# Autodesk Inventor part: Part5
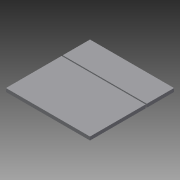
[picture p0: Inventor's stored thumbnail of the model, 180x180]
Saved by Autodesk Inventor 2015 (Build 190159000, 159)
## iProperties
Created: 2015-04
Part Number: Part5
Material: Generic
Document SubType Name: Modeling
Designer: TREINA5
Density: 1 g/cm^3
Appearance: Default
Mass: 129645 g
Surface Area: 48519 cm^2
Volume: 129645 cm^3
Author: TREINA5
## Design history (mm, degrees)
sketch "Sketch1"
  geometry: L1 (13480, 4245.02)-(13480, 3234.98); L2 (13499.999, 4479.966)-(14982.938, 4479.966); L3 (13502.938, 3000)-(13500, 4480); L4 (13499.999, 4499.966)-(14982.938, 4499.966); L5 (14982.938, 4480)-(14982.938, 3000); L6 (12000, 3499.835)-(12000, 3980.098); L7 (12000, 4000)-(12000, 4479.966); L8 (12000, 4479.966)-(12479.966, 4479.966); L9 (11980, 4480)-(11980, 3000); L10 (10500, 3000)-(10500, 4480); L11 (10500, 4480)-(11980, 4480); L12 (12499.868, 4479.966)-(13480, 4479.966); L13 (13480, 3000.034)-(13480, 2999.966); L14 (11500.033, 2980)-(11980, 2980); L15 (11980, 2980)-(11980, 2500); L16 (12000, 1499.966)-(12000, 2480.098); L17 (12000, 1500)-(13480, 1500); L18 (13480, 2745.087)-(13480, 1499.966); L19 (12234.538, 1499.966)-(13480, 1499.966); L20 (12499.868, 2999.966)-(13480, 2999.966); L21 (11480.132, 2979.966)-(13480, 2979.966); L22 (11980, 2480.098)-(11980, 1500); L23 (12000, 2500)-(12000, 2979.966); L24 (10500, 1480)-(11980, 1480); L25 (10500, 1500)-(11980, 1500); L26 (10500, 1500)-(11745.258, 1500); L27 (10480, 2479.966)-(10480, 1499.966); L28 (10500, 1500)-(10500, 2745.087); L29 (10500, 3000)-(11980, 3000); L30 (10500, 2980)-(11480.131, 2980); L31 (9000, 2999.966)-(9480, 2999.966); L32 (8500, 2999.966)-(8980, 2999.966); L33 (9500, 4479.966)-(9500, 2999.966); L34 (9480, 4479.966)-(9480, 2999.966); L35 (8500, 4479.966)-(8980, 4479.966); L36 (8500, 2999.966)-(8500, 4479.966); L37 (8480, 2999.966)-(8480, 4479.966); L38 (7500, 4479.966)-(8480, 4479.966); L39 (7500, 2999.966)-(8480, 2999.966); L40 (13500, 1480)-(14980, 1480); L41 (14980, 1480)-(14980, 0); L42 (13500, 0)-(13500, 1480); L43 (13500, 0)-(14980, 0); L44 (13500, 1500)-(14565.618, 1500); L45 (14979.989, 1500)-(14980, 1500); L46 (13499.999, 2999.966)-(14982.938, 2999.966); L47 (14982.938, 2980)-(14982.938, 1500); L48 (13499.999, 2979.966)-(14982.938, 2979.966); L49 (13497.05, 1499.966)-(14979.989, 1499.966); L50 (13497.05, 1479.966)-(14979.989, 1479.966); L51 (9000, 1500)-(10480, 1500); L52 (9000, 1480)-(10480, 1480); L53 (9000, 1499.966)-(9000, 2979.966); L54 (9000, 1499.966)-(10480, 1499.966); L55 (9480, 2479.966)-(10480, 2479.966); L56 (9500, 2499.966)-(10480, 2499.966); L57 (10480, 2979.966)-(10480, 2499.966); L58 (9500, 2979.966)-(10480, 2979.966); L59 (9500, 2999.966)-(10480, 2999.966); L60 (9500, 2979.966)-(9500, 2499.966); L61 (9480, 2979.966)-(9480, 2479.966); L62 (7500, 1500)-(8980, 1500); L63 (7500, 1480)-(8980, 1480); L64 (7500, 2979.966)-(8480, 2979.966)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; A1 r 509.966 centre (11990, 4489.966) between (12000, 3980.098) and (12499.869, 4480.001); A2 r 490.068 centre (11990, 4489.966) between (12000, 4000) and (12479.967, 4480.001); A3 r 1490.034 centre (11990, 4489.966) between (13277.537, 3740) and (13480, 4479.966); A4 r 1510 centre (11990, 4489.966) between (13300.591, 3740) and (13480, 4245.02); A5 r 1510 centre (11990, 2990.034) between (13480, 3234.98) and (13300.591, 3740); A6 r 1490.034 centre (11990, 2990.034) between (13480, 2999.966) and (13277.536, 3740); A7 r 490.068 centre (11990, 2989.966) between (11500.033, 2980.001) and (11980, 2500); A8 r 490.068 centre (11990, 2989.966) between (12000, 2500) and (12479.967, 2980.001); A9 r 509.966 centre (11990, 2989.966) between (12000, 2480.098) and (12499.869, 2980.001); A10 r 1510 centre (11990, 2990.034) between (12234.538, 1499.966) and (13480, 2745.087); A11 r 1490.034 centre (11990, 2990.034) between (12000, 1500.034) and (13480, 2979.966); A12 r 509.966 centre (11990, 2989.966) between (11480.131, 2980.001) and (11980, 2480.098); A13 r 1490.034 centre (11990, 2990.034) between (10500, 2980.034) and (11980, 1500.034); A14 r 1510 centre (11990, 2990.034) between (10500, 2745.087) and (11745.258, 1500); A15 r 4510.011 centre (14990, 5990) between (14979.989, 1480) and (14980, 1480); A16 r 1510 centre (11990, 2990.034) between (10480.034, 3000.067) and (10480.033, 2999.966); A17 r 509.966 centre (11990, 2989.966) between (12499.869, 2999.932) and (12000, 3499.835); A18 r 490.068 centre (11990, 2989.966) between (12479.967, 2999.932) and (12000, 3479.933); A19 r 1510 centre (2990, 2489.966) between (2980, 3999.933) and (1568.745, 3000); A20 r 1510 centre (4490, 4490.034) between (2980.033, 4500) and (2980.034, 4480); A21 r 1490.034 centre (2990, 2489.966) between (2980, 3979.966) and (1589.964, 2999.966); A22 r 509.966 centre (2990, 4490) between (3000, 3980.132) and (3499.869, 4480.034); A23 r 490.068 centre (2990, 4490) between (3000, 4000.034) and (3479.967, 4480.034); A24 r 1510 centre (2990, 4490) between (4490.002, 4663.473) and (4489.998, 4663.506); A25 r 1510 centre (5990, 4489.966) between (4490.002, 4663.473) and (4489.998, 4663.439); A26 r 1510 centre (2990, 4490) between (4499.967, 4499.966) and (4499.966, 4500.033); A27 r 1510 centre (5990, 4489.966) between (4480.034, 4479.966) and (4480.034, 4479.933); A28 r 1490.034 centre (2990, 4490) between (3000, 3000) and (4480, 4480); A29 r 1510 centre (2990, 4490) between (3234.742, 2999.966) and (4480, 4245.054); A30 r 1510 centre (5990, 2989.966) between (4480.034, 3000) and (4480.034, 2999.966); A31 r 1510 centre (5990, 4489.966) between (7499.966, 4479.933) and (7499.966, 4479.966); A32 r 1510 centre (5990, 2989.966) between (7499.966, 2999.966) and (7499.966, 3000); A33 r 1510 centre (5990, 2989.966) between (6234.946, 1499.966) and (7480, 2745.02); A34 r 1490.034 centre (5990, 2989.966) between (6000, 1499.966) and (7480, 2979.966); A35 r 509.966 centre (5990, 2989.966) between (6000, 2480.098) and (6499.869, 2980.001); A36 r 490.068 centre (5990, 2989.966) between (5500.033, 2980.001) and (5980, 2500); A37 r 509.966 centre (5990, 2989.966) between (5480.131, 2980.001) and (5980, 2480.098); A38 r 490.068 centre (5990, 2989.966) between (6000, 2500) and (6479.967, 2980.001); A39 r 490.068 centre (2990, 2489.966) between (2980, 2979.933) and (2500.033, 2499.932); A40 r 509.966 centre (2990, 2489.966) between (2848.7, 2979.966) and (2480.132, 2479.966); A41 r 1510 centre (5990, 2989.966) between (4500, 2745.02) and (5745.054, 1499.966); A42 r 1490.034 centre (5990, 2989.966) between (4500, 2979.966) and (5980, 1499.966); A43 r 1510 centre (2990, 2489.966) between (1561.726, 2980) and (1500, 2734.913); A44 r 490.068 centre (11990, 4489.966) between (12479.967, 4499.932) and (12000, 4979.933); A45 r 509.966 centre (11990, 4489.966) between (12499.869, 4499.932) and (12000, 4999.835); A46 r 1490.034 centre (11990, 4489.966) between (13480, 4499.966) and (12000, 5979.966); A47 r 1510 centre (11990, 4489.966) between (13480, 4734.913) and (12234.946, 5979.966); A48 r 1490.034 centre (11990, 4489.966) between (11980, 5979.966) and (10500, 4499.966); A49 r 1510 centre (11990, 4489.966) between (11745.054, 5979.966) and (10500, 4734.913); A50 r 509.966 centre (11990, 4489.966) between (11980, 4999.835) and (11480.131, 4499.932); A51 r 490.068 centre (11990, 4489.966) between (11980, 4979.933) and (11500.033, 4499.932); A52 r 2989.933 centre (13489.917, 8990) between (12000, 6397.733) and (13479.998, 6000.083); A53 r 1510 centre (11990, 4489.966) between (10480.034, 4479.966) and (10480.034, 4479.933); A54 r 3010.067 centre (13489.917, 8990) between (10886.462, 7479.198) and (11979.983, 6386.041); A55 r 2989.933 centre (13489.917, 8990) between (10909.766, 7479.198) and (11979.983, 6409.341); A56 r 3010.067 centre (13489.917, 8990) between (12000, 6374.536) and (13149.912, 5999.198); A57 r 2989.933 centre (13489.917, 8990) between (10500, 8980) and (10898.159, 7499.198); A58 r 3010.067 centre (13489.917, 8990) between (10500, 8642.293) and (10874.958, 7499.198); A59 r 3010.067 centre (13489.917, 8990) between (10479.866, 8980) and (10480, 8959.938); A60 r 490.068 centre (5990, 4489.966) between (6479.967, 4499.932) and (6000, 4979.933); A61 r 1490.034 centre (5990, 4489.966) between (7480, 4499.966) and (6000, 5979.966); A62 r 1510 centre (5990, 4489.966) between (7480, 4734.913) and (6234.946, 5979.966); A63 r 2990 centre (-10, 10490) between (1500, 7909.302) and (2570.698, 8980); A64 r 3010 centre (-10, 10490) between (1500, 7886.157) and (2593.843, 8980)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; 7 further points
  constraints: 958 end point, 196 point on circle, 95 point on line, 82 centre point, 24 other
extrude "Extrusion1" new body sketch "Sketch1" distance "d0" = 60; taper "d1" = 0 deg
extrude "Extrusion2" new body sketch "Sketch1" distance "d2" = 60; taper "d3" = 0 deg
body "Solid1"
body "Solid2"
